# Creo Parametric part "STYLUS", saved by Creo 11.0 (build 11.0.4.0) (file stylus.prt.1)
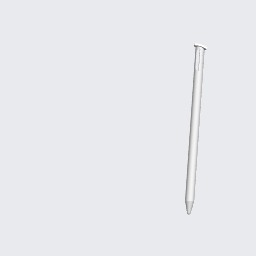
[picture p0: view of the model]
Units: millimeter Kilogram Sec (mmKs); MM, KILOGRAM, SECS

Created from: XX_SOLID_PART_MMKS_NEW_ABS.PRT

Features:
  1. datum plane "RIGHT"
  2. datum plane "TOP"
  3. datum plane "FRONT"
  4. coordinate system
  5. revolve "Revolve 1"
  6. sketch "Sketch 1"
  7. protrusion "Sweep 1"
  8. swept cut "Sweep 2"
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
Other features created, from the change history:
  extruded cut "Extrude 1"
  datum plane "DTM1"
  extrusion "Extrude 2"

Surfaces: 6 cylinder, 5 plane, 4 cone, 4 torus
